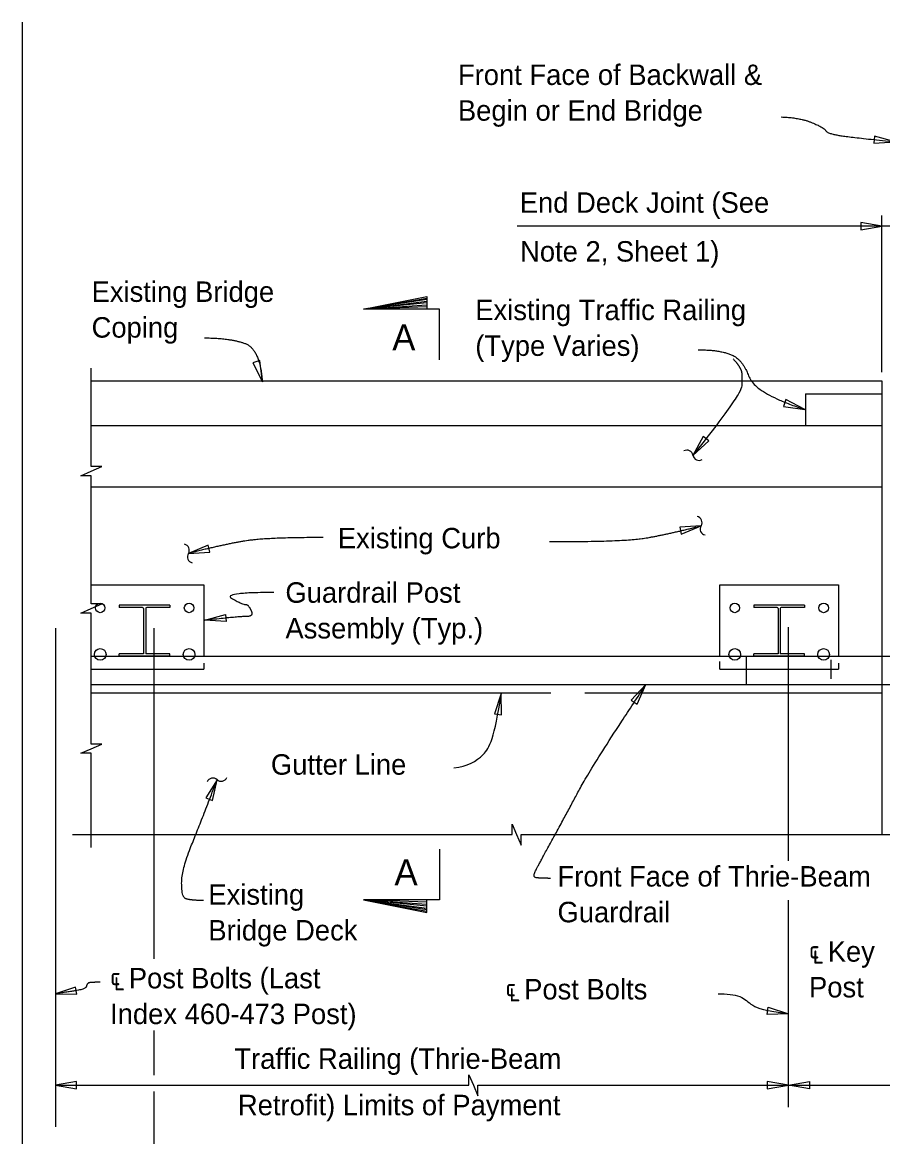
# Model space of a CAD drawing. Extents: x 21526.6 to 21595.9, y 56117 to 56157.3.
# Drawn here: x 21545.72 to 21554.19, y 56142.28 to 56153.26 of the extents above; entities that cross this region are included whole.
import ezdxf

# ---------------------------------------------------------------- set-up
doc = ezdxf.new("R2010")
doc.units = 0
for name, color, linetype in [('AdhocPoint_dp', 7, 'Continuous'), ('Border', 7, 'Continuous'), ('Patterning', 7, 'Continuous'), ('PlotBorder_dp', 7, 'Continuous'), ('TextMisc', 7, 'Continuous')]:
    doc.layers.add(name, color=color, linetype=linetype)

msp = doc.modelspace()

# ---------------------------------------------------------------- linework, layer by layer
at = {"layer": 'AdhocPoint_dp'}
for p, q in [((21554.182, 56149.72), (21546.396, 56149.72)), ((21554.182, 56149.722), (21554.182, 56145.254)), ((21553.432, 56149.595), (21554.182, 56149.595)), ((21546.396, 56149.282), (21554.182, 56149.282)), ((21546.396, 56148.678), (21554.182, 56148.678)), ((21546.395, 56146.648), (21550.921, 56146.648)), ((21551.257, 56146.648), (21554.182, 56146.648))]:
    msp.add_line(p, q, dxfattribs=at)
msp.add_lwpolyline([(21553.432, 56149.595), (21553.432, 56149.282)], dxfattribs=at)
at = {"layer": 'Patterning'}
for p, q in [((21546.042, 56147.287), (21546.042, 56142.373)), ((21547.015, 56144.029), (21547.015, 56147.287)), ((21552.848, 56146.732), (21552.848, 56147.012)), ((21552.848, 56147.012), (21566.396, 56147.012)), ((21553.682, 56146.789), (21553.682, 56146.974)), ((21552.848, 56146.732), (21566.234, 56146.732)), ((21547.015, 56142.884), (21547.015, 56143.322)), ((21547.015, 56136.022), (21547.015, 56142.721))]:
    msp.add_line(p, q, dxfattribs=at)
for points in [[(21546.396, 56146.882), (21547.505, 56146.882)], [(21552.588, 56146.882), (21553.755, 56146.882)]]:
    msp.add_lwpolyline(points, dxfattribs=at)
at = {"layer": 'PlotBorder_dp'}
for p, q in [((21545.716, 56153.256), (21545.716, 56127.317)), ((21554.182, 56149.808), (21554.182, 56151.352)), ((21554.69, 56151.248), (21550.59, 56151.248)), ((21549.076, 56150.429), (21549.701, 56150.539)), ((21549.701, 56150.526), (21549.076, 56150.429)), ((21549.076, 56150.429), (21549.701, 56150.509)), ((21549.701, 56150.491), (21549.076, 56150.429)), ((21549.076, 56150.429), (21549.701, 56150.473)), ((21549.701, 56150.453), (21549.076, 56150.429)), ((21553.263, 56144.993), (21553.263, 56147.297)), ((21549.701, 56144.586), (21549.076, 56144.609)), ((21549.076, 56144.609), (21549.701, 56144.566)), ((21549.701, 56144.547), (21549.076, 56144.609)), ((21549.076, 56144.609), (21549.701, 56144.529)), ((21549.701, 56144.512), (21549.076, 56144.609)), ((21549.076, 56144.609), (21549.701, 56144.499)), ((21553.263, 56142.567), (21553.263, 56144.606))]:
    msp.add_line(p, q, dxfattribs=at)
for points in [[(21554.314, 56152.078), (21554.11, 56152.134), (21554.103, 56152.064)], [(21554.182, 56151.248), (21553.974, 56151.283), (21553.974, 56151.212)], [(21548.081, 56149.712), (21548.056, 56149.922), (21547.988, 56149.902)], [(21553.424, 56149.441), (21553.237, 56149.539), (21553.215, 56149.472)], [(21552.322, 56148.989), (21552.479, 56149.131), (21552.424, 56149.175)], [(21552.402, 56148.295), (21552.192, 56148.282), (21552.207, 56148.213)], [(21547.352, 56148.023), (21547.562, 56148.036), (21547.546, 56148.105)], [(21547.514, 56147.364), (21547.717, 56147.421), (21547.724, 56147.351)], [(21551.859, 56146.731), (21551.714, 56146.577), (21551.773, 56146.538)], [(21550.434, 56146.643), (21550.368, 56146.443), (21550.437, 56146.432)], [(21547.635, 56145.794), (21547.525, 56145.614), (21547.591, 56145.588)], [(21546.042, 56143.683), (21546.253, 56143.68), (21546.242, 56143.75)], [(21553.264, 56143.488), (21553.053, 56143.482), (21553.063, 56143.552)], [(21546.042, 56142.784), (21546.25, 56142.748), (21546.25, 56142.819)], [(21553.263, 56142.784), (21553.054, 56142.819), (21553.054, 56142.748)], [(21553.263, 56142.784), (21553.471, 56142.819), (21553.471, 56142.748)]]:
    msp.add_lwpolyline(points, close=True, dxfattribs=at)
for points in [[(21549.826, 56149.929), (21549.826, 56150.429), (21549.076, 56150.429), (21549.701, 56150.554), (21549.701, 56150.429)], [(21546.396, 56148.32), (21546.396, 56148.789), (21546.292, 56148.789), (21546.396, 56148.834), (21546.499, 56148.879), (21546.396, 56148.879), (21546.396, 56149.848)], [(21546.396, 56146.573), (21546.396, 56147.436), (21546.292, 56147.436), (21546.396, 56147.481), (21546.499, 56147.526), (21546.396, 56147.526), (21546.396, 56148.32)], [(21546.396, 56145.126), (21546.396, 56146.054), (21546.292, 56146.054), (21546.396, 56146.099), (21546.499, 56146.144), (21546.396, 56146.144), (21546.396, 56147.017)], [(21546.211, 56145.254), (21550.54, 56145.254), (21550.54, 56145.357), (21550.585, 56145.254), (21550.63, 56145.15), (21550.63, 56145.254), (21553.591, 56145.254)], [(21553.591, 56145.254), (21558.469, 56145.254), (21558.469, 56145.357), (21558.514, 56145.254), (21558.559, 56145.15), (21558.559, 56145.254), (21560.824, 56145.254)], [(21549.826, 56145.109), (21549.826, 56144.609), (21549.076, 56144.609), (21549.701, 56144.484), (21549.701, 56144.609)], [(21546.042, 56142.784), (21550.114, 56142.784), (21550.114, 56142.887), (21550.159, 56142.784), (21550.204, 56142.68), (21550.204, 56142.784), (21562.137, 56142.784)]]:
    msp.add_lwpolyline(points, dxfattribs=at)
for centre, start, end in [((21552.263, 56148.981), 8.6098, 120.3371), ((21552.381, 56148.999), 188.6098, 300.3371), ((21552.352, 56148.328), 327.2252, 78.9524), ((21552.452, 56148.263), 147.2252, 258.9524), ((21547.302, 56148.055), 327.2252, 78.9524), ((21547.402, 56147.99), 147.2252, 258.9524), ((21547.594, 56145.75), 47.1839, 158.9112), ((21547.675, 56145.838), 227.1839, 338.9112)]:
    msp.add_arc(centre, 0.0596, start, end, dxfattribs=at)
for points, degree in [([(21553.192, 56152.323), (21553.377, 56152.316), (21553.614, 56152.217), (21553.647, 56152.158), (21553.918, 56152.118), (21554.314, 56152.078)], 2), ([(21547.51, 56150.146), (21547.749, 56150.146), (21548.058, 56150.042), (21548.081, 56149.712)], 2), ([(21552.374, 56150.029), (21552.585, 56150.029), (21552.813, 56149.932), (21552.933, 56149.6), (21553.424, 56149.441)], 2), ([(21552.719, 56149.939), (21552.802, 56149.846), (21552.802, 56149.749), (21552.802, 56149.595), (21552.322, 56148.989)], 2), ([(21550.91, 56148.139), (21551.624, 56148.139), (21552.029, 56148.201), (21552.402, 56148.295)], 2), ([(21548.679, 56148.179), (21548.13, 56148.179), (21547.725, 56148.117), (21547.352, 56148.023)], 2), ([(21548.195, 56147.638), (21547.671, 56147.638), (21547.896, 56147.516), (21547.939, 56147.524), (21547.999, 56147.402), (21547.857, 56147.402), (21547.514, 56147.364)], 2), ([(21550.918, 56144.822), (21550.805, 56144.822), (21550.741, 56144.837), (21550.812, 56144.975), (21551.095, 56145.491), (21551.332, 56145.937), (21551.859, 56146.731)], 2), ([(21549.967, 56145.91), (21550.101, 56145.925), (21550.277, 56146.022), (21550.365, 56146.198), (21550.435, 56146.643)], 3), ([(21547.501, 56144.604), (21547.349, 56144.604), (21547.286, 56144.65), (21547.286, 56144.908), (21547.494, 56145.424), (21547.635, 56145.794)], 2), ([(21546.484, 56143.799), (21546.418, 56143.798), (21546.354, 56143.792), (21546.345, 56143.735), (21546.219, 56143.711), (21546.042, 56143.683)], 2), ([(21552.57, 56143.684), (21552.651, 56143.684), (21552.81, 56143.673), (21552.888, 56143.564), (21553.03, 56143.521), (21553.264, 56143.488)], 3)]:
    msp.add_open_spline(points, degree=degree, dxfattribs=at)
at = {"layer": 'TextMisc'}
for p, q in [((21547.171, 56147.512), (21546.671, 56147.512)), ((21546.671, 56147.512), (21546.671, 56147.491)), ((21546.9, 56147.491), (21546.671, 56147.491)), ((21546.911, 56147.481), (21546.911, 56147.033)), ((21546.932, 56147.481), (21546.932, 56147.033)), ((21547.171, 56147.491), (21546.942, 56147.491)), ((21547.171, 56147.512), (21547.171, 56147.491)), ((21553.421, 56147.512), (21552.921, 56147.512)), ((21552.921, 56147.512), (21552.921, 56147.491)), ((21553.15, 56147.491), (21552.921, 56147.491)), ((21553.161, 56147.481), (21553.161, 56147.033)), ((21553.182, 56147.481), (21553.182, 56147.033)), ((21553.421, 56147.491), (21553.192, 56147.491)), ((21553.421, 56147.512), (21553.421, 56147.491)), ((21546.395, 56147.012), (21552.848, 56147.012)), ((21546.911, 56147.033), (21546.671, 56147.033)), ((21546.671, 56147.012), (21546.671, 56147.033)), ((21547.171, 56147.012), (21546.671, 56147.012)), ((21547.171, 56147.033), (21546.932, 56147.033)), ((21547.171, 56147.012), (21547.171, 56147.033)), ((21553.161, 56147.033), (21552.921, 56147.033)), ((21552.921, 56147.012), (21552.921, 56147.033)), ((21553.421, 56147.012), (21552.921, 56147.012)), ((21553.421, 56147.033), (21553.182, 56147.033)), ((21553.421, 56147.012), (21553.421, 56147.033)), ((21546.395, 56146.732), (21552.848, 56146.732))]:
    msp.add_line(p, q, dxfattribs=at)
for points in [[(21546.396, 56147.715), (21547.505, 56147.715), (21547.505, 56147.017)], [(21552.588, 56147.017), (21552.588, 56147.715), (21553.755, 56147.715), (21553.755, 56147.01)], [(21547.505, 56146.943), (21547.505, 56146.882)], [(21552.588, 56146.882), (21552.588, 56146.959)], [(21553.755, 56146.943), (21553.755, 56146.882)]]:
    msp.add_lwpolyline(points, dxfattribs=at)
for centre, radius in [((21546.484, 56147.486), 0.0469), ((21547.359, 56147.486), 0.0469), ((21552.734, 56147.486), 0.0469), ((21553.609, 56147.486), 0.0469), ((21546.484, 56147.028), 0.0573), ((21547.359, 56147.028), 0.0573), ((21552.734, 56147.028), 0.0573), ((21553.609, 56147.028), 0.0573)]:
    msp.add_circle(centre, radius, dxfattribs=at)
for centre, start, end in [((21546.9, 56147.481), 0, 90), ((21546.942, 56147.481), 90, 180), ((21553.15, 56147.481), 0, 90), ((21553.192, 56147.481), 90, 180)]:
    msp.add_arc(centre, 0.0104, start, end, dxfattribs=at)

# ---------------------------------------------------------------- texts
at = {"layer": 'Border'}
for s, height, p in [('End Deck Joint (See', 0.2016, (21550.616, 56151.379)), ('Note 2, Sheet 1)', 0.2016, (21550.619, 56150.898)), ('A', 0.256, (21549.36, 56150.023)), ('Existing Curb', 0.2016, (21548.824, 56148.073)), ('Gutter Line', 0.2016, (21548.165, 56145.843)), ('A', 0.256, (21549.382, 56144.754)), ('℄ Key ', 0.2016, (21553.465, 56144.001)), ('℄ Post Bolts', 0.2016, (21550.475, 56143.629)), ('Post', 0.2016, (21553.465, 56143.649))]:
    msp.add_text(s, height=height, dxfattribs=at).set_placement(p)
at = {"layer": 'PlotBorder_dp'}
for s, p in [('Front Face of Backwall &', (21550.007, 56152.638)), ('Begin or End Bridge', (21550.007, 56152.286)), ('Existing Bridge ', (21546.399, 56150.501)), ('Existing Traffic Railing', (21550.178, 56150.321)), ('Coping ', (21546.399, 56150.149)), ('(Type Varies)', (21550.178, 56149.969)), ('Guardrail Post ', (21548.308, 56147.537)), ('Assembly (Typ.)', (21548.308, 56147.185)), ('Front Face of Thrie-Beam ', (21550.988, 56144.741)), ('Existing ', (21547.549, 56144.562)), ('Guardrail', (21550.988, 56144.389)), ('Bridge Deck', (21547.549, 56144.21)), ('℄ Post Bolts (Last ', (21546.581, 56143.738)), ('Index 460-473 Post)', (21546.581, 56143.386)), ('Traffic Railing (Thrie-Beam', (21547.805, 56142.945)), ('Retrofit) Limits of Payment', (21547.84, 56142.488))]:
    msp.add_text(s, height=0.2016, dxfattribs=at).set_placement(p)

doc.saveas('drawing.dxf')
